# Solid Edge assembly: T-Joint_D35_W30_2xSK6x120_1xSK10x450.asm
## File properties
Author: fknapp
Template: iso metric assembly.asm
Last saved by: fknapp
Revision: 11
Application: Solid Edge
Username: fknapp
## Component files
T-Joint_D35_W30.par
SK Schraube 10x450_ohne_Gewinde_22042020.par
SK Schraube 6x120_ohne_Gewinde.par
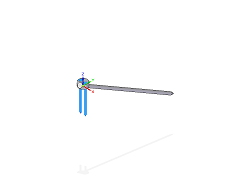
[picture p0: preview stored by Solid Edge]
